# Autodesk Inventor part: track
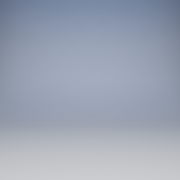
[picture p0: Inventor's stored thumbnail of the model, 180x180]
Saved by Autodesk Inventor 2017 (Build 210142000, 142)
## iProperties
Created: 2017-04
Part Number: track
Material: Generic
Document SubType Name: Modeling
Designer: 1717440
Density: 1 g/cm^3
Appearance: Default
Author: 1717440
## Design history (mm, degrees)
sketch "Sketch1"
  geometry: L1 (-53.138, 79.988)-(-53.138, 86.338); L2 (-53.138, 86.338)-(-81.713, 86.338); L3 (-53.138, 79.988)-(-81.713, 79.988); L4 (-53.138, 79.519)-(-81.713, 79.519); L5 (-81.713, 86.807)-(-53.138, 86.807); L6 (-53.138, 78.111)-(-81.713, 78.111); L7 (-81.713, 88.216)-(-53.138, 88.216); A1 r 3.175 centre (-53.138, 83.163) between (-53.138, 79.988) and (-53.138, 86.338) reference; A2 r 3.175 centre (-81.713, 83.163) between (-81.713, 86.338) and (-81.713, 79.988); A3 r 3.175 centre (-53.138, 83.163) between (-53.138, 79.988) and (-53.138, 86.338); A4 r 3.644 centre (-81.713, 83.163) between (-81.713, 86.807) and (-81.713, 79.519); A5 r 5.052 centre (-81.713, 83.163) between (-81.713, 88.216) and (-81.713, 78.111); A6 r 3.644 centre (-53.138, 83.163) between (-53.138, 79.519) and (-53.138, 86.807); A7 r 5.052 centre (-53.138, 83.163) between (-53.138, 78.111) and (-53.138, 88.216); 1 further point
  constraints: 14 end point, 14 point on circle, 6 centre point, 1 coincident, 1 concentric, 1 horizontal, 1 perpendicular, 1 tangent, 1 vertical, 4 other
  dimensions: "d0" = 28.575 distance of L1.end L2.end; "d1" = 28.575 distance of L1.start L3.end; "d2" = 0.469 radial gap between concentric circles of A2 A4; "d3" = 1.4084 radial gap between concentric circles of A4 A5
extrude "Extrusion1" new body sketch "Sketch1" distance "d4" = 2; taper "d5" = 0 deg
body "Solid1"
node "Reference1"
